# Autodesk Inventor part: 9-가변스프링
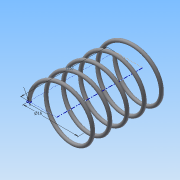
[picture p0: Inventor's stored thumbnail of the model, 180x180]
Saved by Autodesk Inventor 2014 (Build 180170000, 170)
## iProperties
Created: 2015-06
Part Number: 9-가변스프링
Material: 강철, 연강
Document SubType Name: Modeling
Designer: Administrator
Density: 7.86 g/cm^3
Appearance: 강철
Mass: 1.53609 g
Surface Area: 7.89657 cm^2
Volume: 0.195431 cm^3
Author: Administrator
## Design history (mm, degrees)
sketch "스케치1"
  geometry: L1 (0, 0)-(-8, 0); L2 (-8, 0)-(-8, 21.5); L3 (-8, 21.5)-(0, 21.5); L4 (0, 21.5)-(0, 0); C1 r 0.5 at (-8, 0)
  constraints: 8 end point, 2 parallel, 1 centre point, 1 coincident, 1 horizontal, 1 perpendicular
  dimensions: "d0" = 1 diameter of C1; "d1" = 16 diameter of L2 L4; "d2" = 21.5 distance of L1.end L2.end (derived)
feature "코일1" sketch "스케치1" pitch "d3" = 10; turns "d5" = 5; dims "d4" = 21.5 (= d2), "d6" = 0, angle "d7" = 90 deg, angle "d8" = 90 deg, "d9" = 0, "d10" = 0
sketch "스케치2"
  geometry: L1 (8.5, 0)-(7.5, 0) reference; 1 further point
  constraints: 1 horizontal alignment
extrude "돌출1" cut sketch "스케치2" stored distance "d11" = 10; taper "d12" = 0 deg
node "작업 평면1"
sketch "스케치3"
  geometry: L1 (7.5, 0)-(8.5, 0) reference; 1 further point
  constraints: 1 horizontal alignment
extrude "돌출2" cut sketch "스케치3" stored distance "d14" = 10; taper "d15" = 0 deg
node "솔리드1"
node "절단 모서리 투영1"
node "절단 모서리 투영2"
other parameters: "d13" = 21.5 (= d2)
